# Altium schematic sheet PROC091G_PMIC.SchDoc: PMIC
size 431 x 279 mm; Date: Not shown in title block; ApprovedBy: Not shown in title block; CheckedBy: Not shown in title block; Author: Not shown in title block; CompanyName: Not shown in title block; DrawnBy: Antony/Bala; Engineer: Not shown in title block; Organization: Not shown in title block; Address1: Not shown in title block; Address2: Not shown in title block; Address3: Not shown in title block; Address4: Not shown in title block; DocumentNumber: 5; Revision: Use project parameter SCH_Rev; SheetNumber: 5; SheetTotal: 12; PageSetup: Record=PageOptions¦CenterHorizontal=True¦CenterVertical=True¦PrintScale=1.00¦XCorrection=1.00¦YCorrection=1.00¦PrintKind=0¦BorderSize=5000000¦LeftOffset=0¦BottomOffset=0¦Orientation=2¦PaperLength=1000¦PaperWidth=1000¦Scale=100¦PaperSource=15¦PrintQuality=600¦MediaType=1¦DitherType=10¦PaperKind=Letter¦PrintScaleMode=1
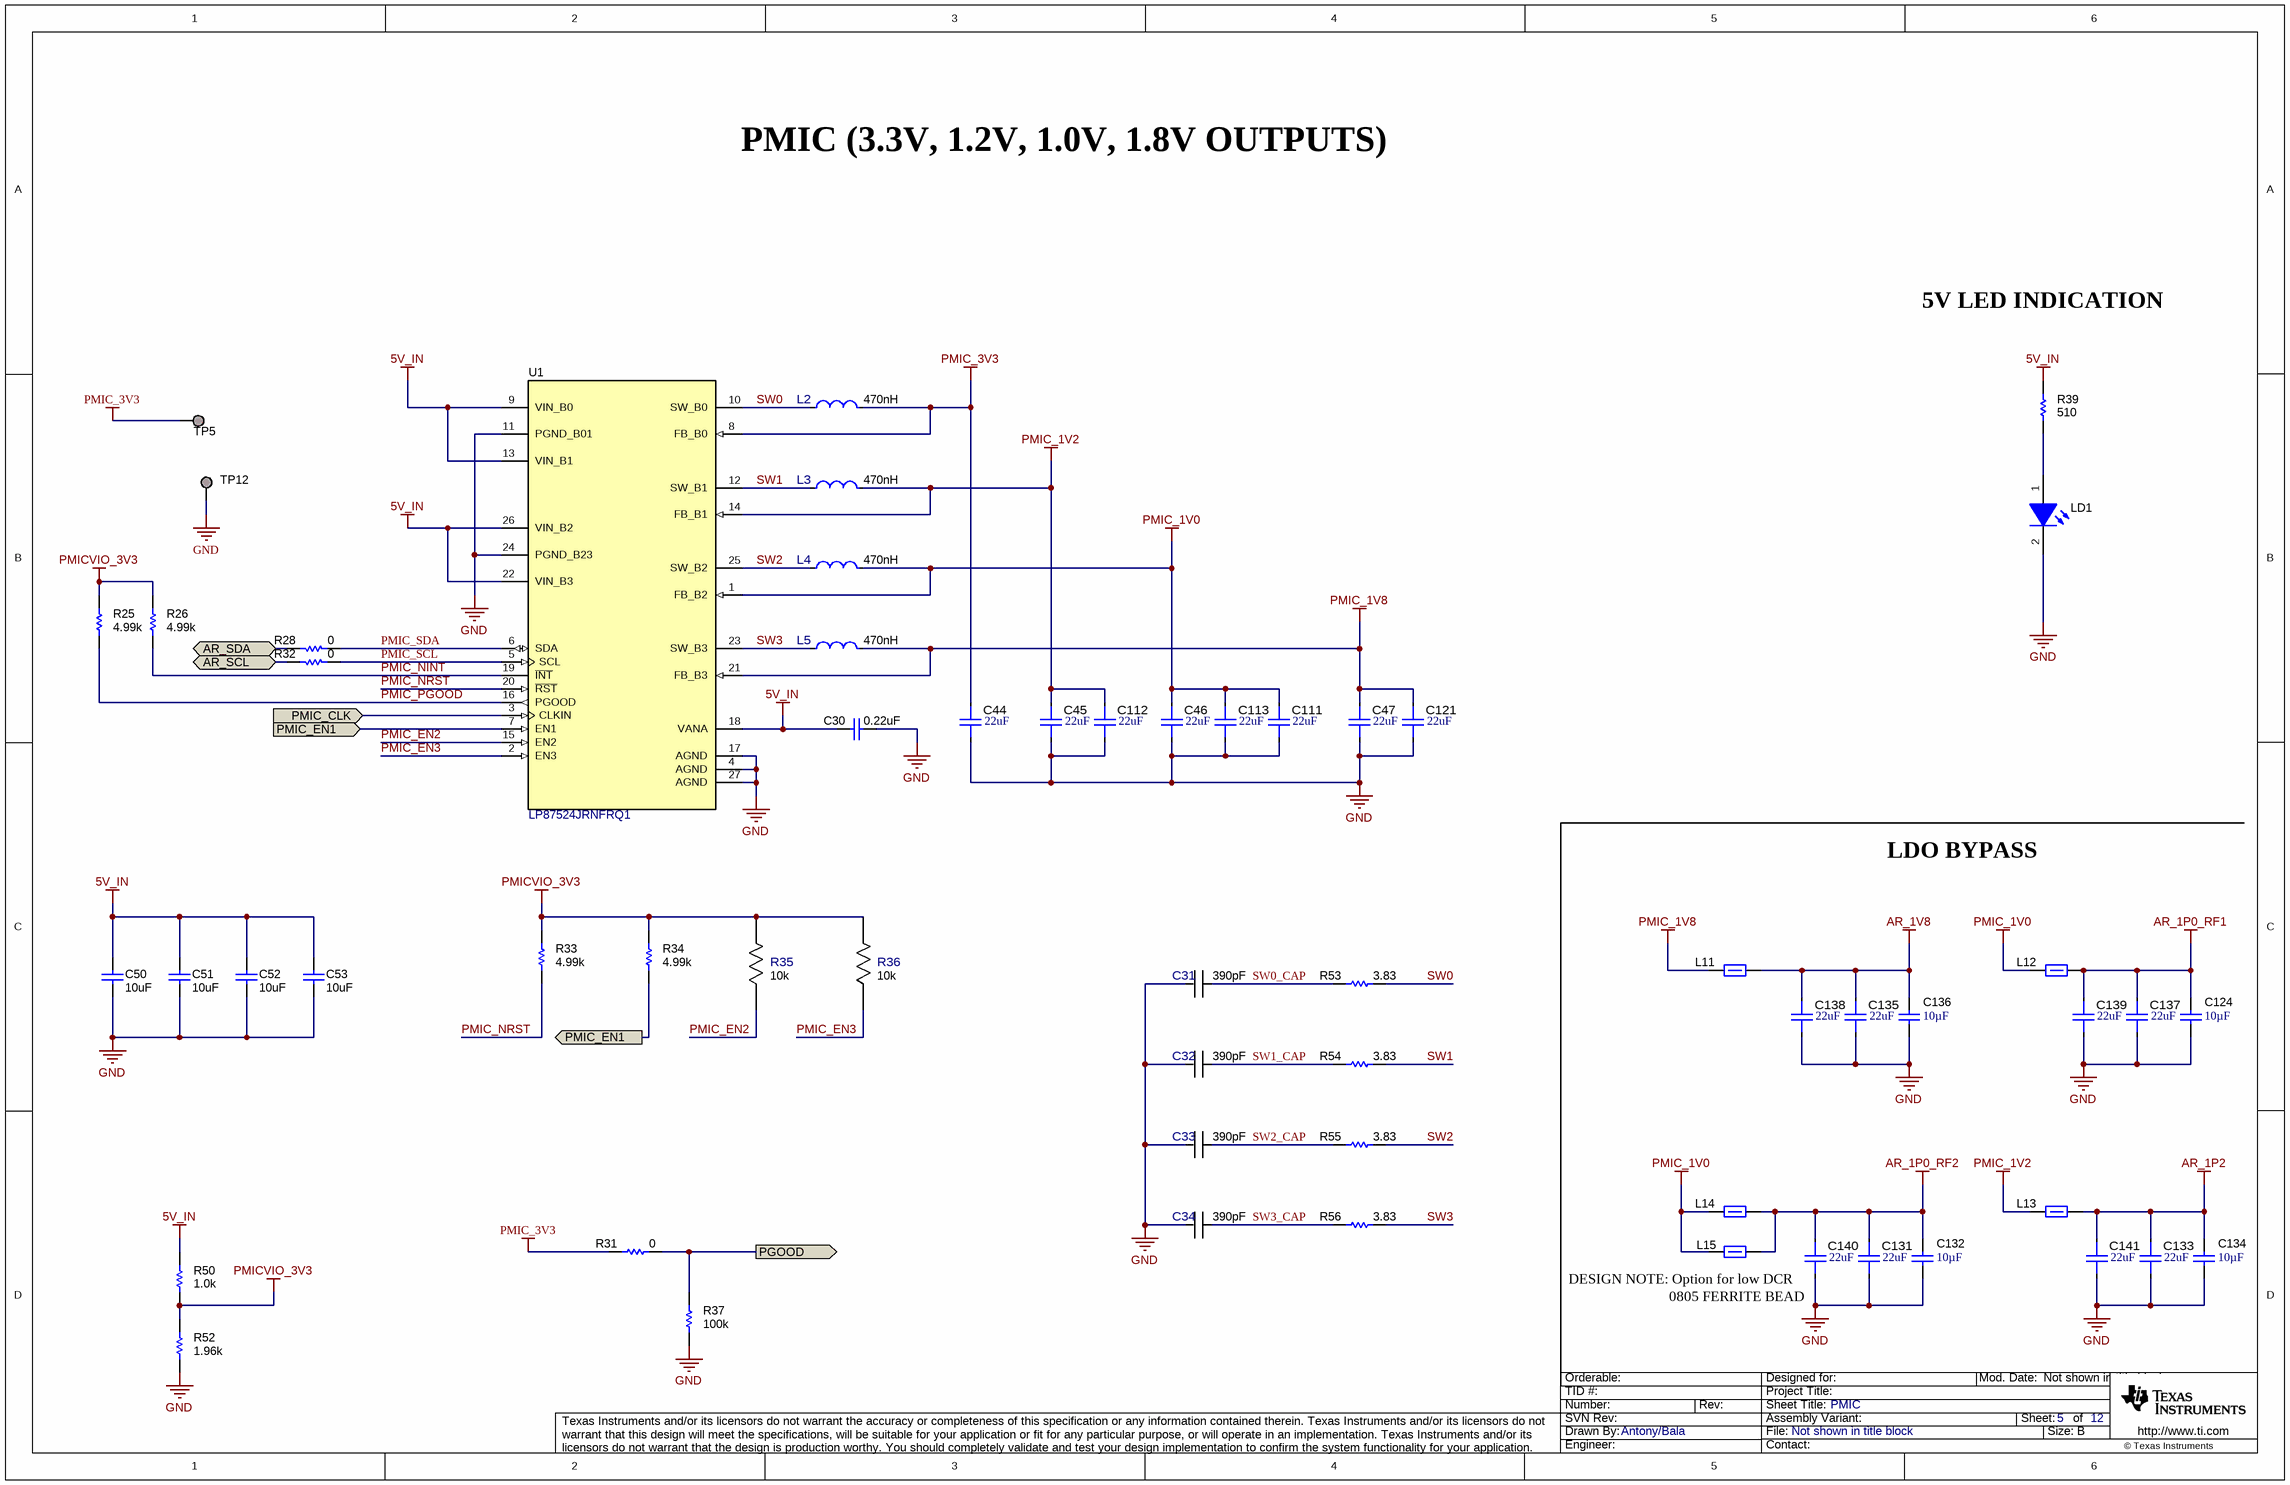
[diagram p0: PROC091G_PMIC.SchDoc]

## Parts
C30  value 0.22uF  [0201_033L]  (hidden comment: LMK063BJ224MP-F)
C31  Cap_F: 390pF  [FP-TMK063CG391JT-F_0201 (0603 Metric)-IPC_C]  (hidden comment: TMK063CG391JT-F)
C32  Cap_F: 390pF  [FP-TMK063CG391JT-F_0201 (0603 Metric)-IPC_C]  (hidden comment: TMK063CG391JT-F)
C33  Cap_F: 390pF  [FP-TMK063CG391JT-F_0201 (0603 Metric)-IPC_C]  (hidden comment: TMK063CG391JT-F)
C34  Cap_F: 390pF  [FP-TMK063CG391JT-F_0201 (0603 Metric)-IPC_C]  (hidden comment: TMK063CG391JT-F)
C44  ValueDisplayed: 22uF  [FP-CGA4J1X7T0J226M125AC_0805-MFG]  (hidden comment: CGA4J1X7T0J226M125AC)
C45  ValueDisplayed: 22uF  [FP-CGA4J1X7T0J226M125AC_0805-MFG]  (hidden comment: CGA4J1X7T0J226M125AC)
C46  ValueDisplayed: 22uF  [FP-CGA4J1X7T0J226M125AC_0805-MFG]  (hidden comment: CGA4J1X7T0J226M125AC)
C47  ValueDisplayed: 22uF  [FP-CGA4J1X7T0J226M125AC_0805-MFG]  (hidden comment: CGA4J1X7T0J226M125AC)
C50  value 10uF  [0402_070]  (hidden comment: CL05A106MP5NUNC)
C51  value 10uF  [0402_070]  (hidden comment: CL05A106MP5NUNC)
C52  value 10uF  [0402_070]  (hidden comment: CL05A106MP5NUNC)
C53  value 10uF  [0402_070]  (hidden comment: CL05A106MP5NUNC)
C111  ValueDisplayed: 22uF  [FP-CGA4J1X7T0J226M125AC_0805-MFG]  (hidden comment: CGA4J1X7T0J226M125AC)
C112  ValueDisplayed: 22uF  [FP-CGA4J1X7T0J226M125AC_0805-MFG]  (hidden comment: CGA4J1X7T0J226M125AC)
C113  ValueDisplayed: 22uF  [FP-CGA4J1X7T0J226M125AC_0805-MFG]  (hidden comment: CGA4J1X7T0J226M125AC)
C121  ValueDisplayed: 22uF  [FP-CGA4J1X7T0J226M125AC_0805-MFG]  (hidden comment: CGA4J1X7T0J226M125AC)
C124  Cap_F: 10µF  [0805_HV]  (hidden comment: GCM21BR71A106KE22L)
C131  ValueDisplayed: 22uF  [FP-CGA4J1X7T0J226M125AC_0805-MFG]  (hidden comment: CGA4J1X7T0J226M125AC)
C132  Cap_F: 10µF  [0805_HV]  (hidden comment: GCM21BR71A106KE22L)
C133  ValueDisplayed: 22uF  [FP-CGA4J1X7T0J226M125AC_0805-MFG]  (hidden comment: CGA4J1X7T0J226M125AC)
C134  Cap_F: 10µF  [0805_HV]  (hidden comment: GCM21BR71A106KE22L)
C135  ValueDisplayed: 22uF  [FP-CGA4J1X7T0J226M125AC_0805-MFG]  (hidden comment: CGA4J1X7T0J226M125AC)
C136  Cap_F: 10µF  [0805_HV]  (hidden comment: GCM21BR71A106KE22L)
C137  ValueDisplayed: 22uF  [FP-CGA4J1X7T0J226M125AC_0805-MFG]  (hidden comment: CGA4J1X7T0J226M125AC)
C138  ValueDisplayed: 22uF  [FP-CGA4J1X7T0J226M125AC_0805-MFG]  (hidden comment: CGA4J1X7T0J226M125AC)
C139  ValueDisplayed: 22uF  [FP-CGA4J1X7T0J226M125AC_0805-MFG]  (hidden comment: CGA4J1X7T0J226M125AC)
C140  ValueDisplayed: 22uF  [FP-CGA4J1X7T0J226M125AC_0805-MFG]  (hidden comment: CGA4J1X7T0J226M125AC)
C141  ValueDisplayed: 22uF  [FP-CGA4J1X7T0J226M125AC_0805-MFG]  (hidden comment: CGA4J1X7T0J226M125AC)
L2  Ind_H: 470nH  [FP-MCKK2012TR47M_0805 (2012 Metric)-IPC_C]  (hidden comment: MCKK2012TR47M)
L3  Ind_H: 470nH  [FP-MCKK2012TR47M_0805 (2012 Metric)-IPC_C]  (hidden comment: MCKK2012TR47M)
L4  Ind_H: 470nH  [FP-MCKK2012TR47M_0805 (2012 Metric)-IPC_C]  (hidden comment: MCKK2012TR47M)
L5  Ind_H: 470nH  [FP-MCKK2012TR47M_0805 (2012 Metric)-IPC_C]  (hidden comment: MCKK2012TR47M)
L11  BLM18KG121TH1D  [0603]  (value not drawn)
L12  BLM18KG121TH1D  [0603]  (value not drawn)
L13  BLM18KG121TH1D  [0603]  (value not drawn)
L14  BLM18KG121TH1D  [0603]  (value not drawn)
L15  BLM21PG221SN1D  [0805L]  (value not drawn)
LD1  APHHS1005CGCK  [APHHS1005_Green]  (value not drawn)
R25  value 4.99k  [0201L]  (hidden comment: RC0201FR-074K99L)
R26  value 4.99k  [0201L]  (hidden comment: RC0201FR-074K99L)
R28  Res_ohm: 0  [FP-RC0201JR-070RL_0201 (0603 Metric)-MFG]  (hidden comment: RC0201JR-070RL)
R31  Res_ohm: 0  [FP-RC0201JR-070RL_0201 (0603 Metric)-MFG]  (hidden comment: RC0201JR-070RL)
R32  Res_ohm: 0  [FP-RC0201JR-070RL_0201 (0603 Metric)-MFG]  (hidden comment: RC0201JR-070RL)
R33  value 4.99k  [0201L]  (hidden comment: RC0201FR-074K99L)
R34  value 4.99k  [0201L]  (hidden comment: RC0201FR-074K99L)
R35  Res_ohm: 10k  [FP-RR0306P-103-D_0201-IPC_C]  (hidden comment: RR0306P-103-D)
R36  Res_ohm: 10k  [FP-RR0306P-103-D_0201-IPC_C]  (hidden comment: RR0306P-103-D)
R37  value 100k  [0201L]  (hidden comment: CRCW0201100KFKED)
R39  value 510  [0201L]  (hidden comment: RC0201JR-07510RL)
R50  value 1.0k  [0201L]  (hidden comment: RC0201JR-071KL)
R52  value 1.96k  [0201L]  (hidden comment: RC0201FR-071K96L)
R53  Res_ohm: 3.83  [FP-RC0402FR-073R83L_0402 (1005 Metric)-IPC_C]  (hidden comment: RC0402FR-073R83L)
R54  Res_ohm: 3.83  [FP-RC0402FR-073R83L_0402 (1005 Metric)-IPC_C]  (hidden comment: RC0402FR-073R83L)
R55  Res_ohm: 3.83  [FP-RC0402FR-073R83L_0402 (1005 Metric)-IPC_C]  (hidden comment: RC0402FR-073R83L)
R56  Res_ohm: 3.83  [FP-RC0402FR-073R83L_0402 (1005 Metric)-IPC_C]  (hidden comment: RC0402FR-073R83L)
TP5  TESTPOINT  [TP_25MIL-SMT]  (value not drawn)  (no BOM)
TP12  TESTPOINT  [TP_VIA_060RND040]  (value not drawn)  (no BOM)
U1  LP87524JRNFRQ1  [RNF0026C]

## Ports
AR_SCL (bidir), AR_SDA (bidir), PGOOD (out), PMIC_CLK (in), PMIC_EN1 (in), PMIC_EN1 (out)

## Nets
5V_IN: C30.1 C50.1 C51.1 C52.1 C53.1 R39.1 R50.2 U1.9(VIN_B0) U1.13(VIN_B1) U1.18(VANA) U1.22(VIN_B3) U1.26(VIN_B2)
AR_1P0_RF1: C124.1 C137.1 C139.1 L12.2
AR_1P0_RF2: C131.1 C132.1 C140.1 L14.2 L15.2
AR_1P2: C133.1 C134.1 C141.1 L13.2
AR_1V8: C135.1 C136.1 C138.1 L11.2
GND: C30.2 C31.2 C32.2 C33.2 C34.2 C44.2 C45.2 C46.2 C47.2 C50.2 C51.2 C52.2 C53.2 C111.2 C112.2 C113.2 C121.2 C124.2 C131.2 C132.2 C133.2 C134.2 C135.2 C136.2 C137.2 C138.2 C139.2 C140.2 C141.2 LD1.2(K) R37.1 R52.1 TP12.1 U1.4(AGND) U1.11(PGND_B01) U1.17(AGND) U1.24(PGND_B23) U1.27(AGND)
PMIC_1V0: C46.1 C111.1 C113.1 L4.1 L12.1 L14.1 L15.1 U1.1(FB_B2)
PMIC_1V2: C45.1 C112.1 L3.1 L13.1 U1.14(FB_B1)
PMIC_1V8: C47.1 C121.1 L5.1 L11.1 U1.21(FB_B3)
PMIC_3V3: C44.1 L2.1 R31.2 TP5.1 U1.8(FB_B0)
PMICVIO_3V3: R25.2 R26.2 R33.2 R34.2 R35.2 R36.2 R50.1 R52.2
AR_SCL: R32.1 ; port AR_SCL
AR_SDA: R28.1 ; port AR_SDA
PGOOD: R31.1 R37.2 ; port PGOOD
PMIC_CLK: U1.3(CLKIN) ; port PMIC_CLK
PMIC_EN1: R34.1 U1.7(EN1) ; port PMIC_EN1
PMIC_EN2: R35.1 U1.15(EN2)
PMIC_EN3: R36.1 U1.2(EN3)
PMIC_NINT: R26.1 U1.19(~{INT})
PMIC_NRST: R33.1 U1.20(~{RST})
PMIC_PGOOD: R25.1 U1.16(PGOOD)
PMIC_SCL: R32.2 U1.5(SCL)
PMIC_SDA: R28.2 U1.6(SDA)
SW0: L2.2 R53.2 U1.10(SW_B0)
SW0_CAP: C31.1 R53.1
SW1: L3.2 R54.2 U1.12(SW_B1)
SW1_CAP: C32.1 R54.1
SW2: L4.2 R55.2 U1.25(SW_B2)
SW2_CAP: C33.1 R55.1
SW3: L5.2 R56.2 U1.23(SW_B3)
SW3_CAP: C34.1 R56.1
NetLD1_1: LD1.1(A) R39.2

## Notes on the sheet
- PMIC (3.3V, 1.2V, 1.0V, 1.8V OUTPUTS)
- 5V LED INDICATION
- LDO BYPASS
- DESIGN NOTE: Option for low DCR
- 0805 FERRITE BEAD

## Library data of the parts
C30 = CMP-0009781-1: CAP, CERM, 0.22 uF, 10 V, +/- 20%, X5R, 0201; Manufacturer: Taiyo Yuden; AEC Category: Q200; AEC Qualified: N; Cap_Case: 0201; Cap_F: 220nF; SizeArea_mm2: 0.18; SizeAreaWB_mm2: 2.08; SizeX_mm: 0.6; SizeY_mm: 0.3; SizeZ_mm: 0.33; TaMax_C: 85°C; TaMin_C: -55°C; U/M: EA; Value1: Unknown; Value2: 10V
C31-C34 = CMP-0086438-1: CAP CER 390PF 25V C0G/NP0 0201; Manufacturer: Taiyo Yuden; AEC Qualified: No; SizeZ_mm: 0.33mm; Symbol Name: SYM-TMK063CG391JT-F; TempCo: 30ppm/°C; Tolerance_%: 5%
C44-C47 C111-C113 C121 C131 C133 C135 C137-C141 = CMP-0091983-1: 22µF ±20% 6.3V Ceramic Capacitor X7T 0805 (2012 Metric); Manufacturer: TDK; AEC Qualified: Yes; AEC Grade: Grade 1; TempCo: +22/-33%; SizeZ_mm: 1.55mm
C50-C53 = CMP-0006339-4: CAP, CERM, 10 uF, 10 V, +/- 20%, X5R, 0402; Manufacturer: Samsung Electro-Mechanics; AEC Category: Q200; AEC Qualified: N; Cap_Case: 0402; Cap_F: 10µF; SizeArea_mm2: 0.5; SizeAreaWB_mm2: 3; SizeX_mm: 1; SizeZ_mm: 0.6; TaMax_C: 85°C; TaMin_C: -55°C; U/M: EA; Value1: Unknown; Value2: 10V
C124 C132 C134 C136 = CMP-0008017-1: CAP, CERM, 10 uF, 10 V, +/- 10%, X7R, 0805; Manufacturer: MuRata; TaMin_C: -55°C; Polarized: N; SizeAreaWB_mm2: 6.75; Value1: Unknown; U/M: EA; Value: 10uF; TaMax_C: 125°C; SizeZ_mm: 1.45; SizeX_mm: 2; SizeY_mm: 1.25; Cap_Case: 0805; Value2: 10V; SizeArea_mm2: 2.5; AEC Category: Q200
L2-L5 = CMP-0087178-1: FIXED IND 470NH 4.5A 39 MOHM SMD; Manufacturer: Taiyo Yuden; AEC Qualified: No; DCR_ohm: 0.032; Irms: 3.1A; Material: Metal; SizeZ_mm: 1mm; Symbol Name: SYM-MCKK2012TR47M
L11-L14 = CMP-0077879-1: Ferrite Bead, 120 ohm @ 100 MHz, 1.9 A, 0603; Manufacturer: MuRata; ZTyp@100MHz_Ohm: 120; SizeAreaWB_mm2: 4.68; DCR_ohm: 0.04; Value1: 0.04 ohm; Value: 120 ohm; Imax_A: 1.9A; SizeZ_mm: 1.0; SizeX_mm: 1.6; SizeY_mm: 0.8; SizeArea_mm2: 1.28
L15 = CMP-0003363-1: Ferrite Bead, 220 ohm @ 100 MHz, 2 A, 0805; Manufacturer: MuRata; ZTyp@100MHz_Ohm: 220; SizeAreaWB_mm2: 6.75; DCR_ohm: 0.045; Value1: 0.045 ohm; Value: 220 ohm; Imax_A: 2A; SizeZ_mm: 1.45; SizeX_mm: 2; SizeY_mm: 1.25; SizeArea_mm2: 2.5
LD1 = CMP-0067682-2: LED, Green, SMD; Manufacturer: Kingbright; Angle: 120.0; Power_TotalModule: 75mW; SizeZ_mm: 0.6; Vf_V: 2.1V; Vr_V: 5V; Io_A: 20mA; Ir_A: 10µA; SizeArea_mm2: 0.5; SizeAreaWB_mm2: 3.0; SizeX_mm: 1.0; Tjmax_C: 85°C; Value1: 0.075W
R25 R26 R33 R34 = CMP-0027745-1: RES, 4.99 k, 1%, 0.05 W, 0201; Manufacturer: Yageo America; AEC Category: Q200; AEC Qualified: N; EIA_Code: E96; Power_W: 50mW; SizeArea_mm2: 0.18; SizeX_mm: 0.6; SizeY_mm: 0.3; SizeZ_mm: 0.26; TempCo: 200 ppm/C; U/M: EA; Value2: 0.05W; Value_Code: 4k99; VDC_V: 25V
R28 R31 R32 = CMP-0086442-2: RES SMD 0 OHM JUMPER 1/20W 0201; Manufacturer: Yageo; AEC Qualified: No; Power_W: 50mW; SizeZ_mm: 0.26mm; TempCo: 200ppm/°C; Tolerance_%: 5%; VDC_V: 25V
R35 R36 = CMP-0088002-1: 10 kOhms ±0.5% 0.05W, 1/20W Chip Resistor 0201 (0603 Metric)  Thin Film; Manufacturer: Susumu; AEC Qualified: No; Power_W: 50mW; SizeZ_mm: 0.26mm; Symbol Name: SYM-RR0306P-103-D; TempCo: 25ppm/°C; VDC_V: 15V
R37 = CMP-0027261-3: RES, 100 k, 1%, 0.05 W, 0201; Manufacturer: Vishay-Dale; AEC Category: Q200; AEC Qualified: N; EIA_Code: E96; Power_W: 50mW; SizeArea_mm2: 0.18; SizeX_mm: 0.6; SizeY_mm: 0.3; SizeZ_mm: 0.26; TempCo: 100 ppm/C; Value2: 0.05W; VDC_V: 30V
R39 = CMP-0027137-1: RES, 510, 5%, 0.05 W, 0201; Manufacturer: Yageo America; AEC Category: Q200; AEC Qualified: N; EIA_Code: E24; Power_W: 50mW; SizeArea_mm2: 0.18; SizeX_mm: 0.6; SizeY_mm: 0.3; SizeZ_mm: 0.26; TempCo: 200 ppm/C; U/M: EA; Value2: 0.05W; Value_Code: 510R; VDC_V: 25V
R50 = CMP-0027052-1: RES, 1.0 k, 5%, 0.05 W, 0201; Manufacturer: Yageo America; AEC Category: Q200; AEC Qualified: N; EIA_Code: E24; Power_W: 50mW; Res_ohm: 1k; SizeArea_mm2: 0.18; SizeX_mm: 0.6; SizeY_mm: 0.3; SizeZ_mm: 0.26; TempCo: 200 ppm/C; U/M: EA; Value2: 0.05W; Value_Code: 1k00; VDC_V: 25V
R52 = CMP-0027452-1: RES, 1.96 k, 1%, 0.05 W, 0201; Manufacturer: Yageo America; AEC Category: Q200; AEC Qualified: N; EIA_Code: E96; Power_W: 50mW; SizeArea_mm2: 0.18; SizeX_mm: 0.6; SizeY_mm: 0.3; SizeZ_mm: 0.26; TempCo: 200 ppm/C; U/M: EA; Value2: 0.05W; Value_Code: 1k96; VDC_V: 25V
R53-R56 = CMP-0086444-2: RES Thick Film SMD 3.83Ω 1% 1/16W 0402 200ppm/°C; Manufacturer: Yageo; AEC Qualified: No; Power_W: 63mW; VDC_V: 50V; SizeZ_mm: 0.4mm
TP5 TP12 = CMP-0078143-3: TEST POINT.  No entry in BOM.
U1 = CMP-0079120-2: 4-A + 2.5-A + Two 1.5-A Buck Converters With Integrated Switches, RNF0026C (VQFN-HR-26); Alternate PartNumber: LP87524JRNFTQ1; Alternate Manufacturer: Texas Instruments; SizeAreaWB_mm2: 27.5; SizeZ_mm: 0.9; SizeX_mm: 4; SizeY_mm: 4.5; SizeArea_mm2: 18; CompType: IC; AEC Qualified: Y; AEC Category: Q200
